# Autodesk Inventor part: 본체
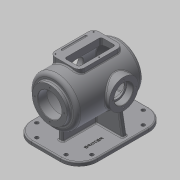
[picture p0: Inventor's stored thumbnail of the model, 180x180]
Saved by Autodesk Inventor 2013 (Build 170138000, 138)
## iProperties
Created: 2016-02
Part Number: 본체
Material: 일반
Document SubType Name: Modeling
Designer: mduedu
Density: 1 g/cm^3
Mass: 1523.86 g
Surface Area: 2907.51 cm^2
Volume: 1523.86 cm^3
Author: mduedu
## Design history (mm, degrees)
sketch "스케치2"
  geometry: L1 (0, 100)-(0, -100); L2 (65, -75.993)-(65, 100); L3 (65, 100)-(0, 100); A1 r 100 centre (0, 0) between (0, -100) and (65, -75.993); 2 further points
  constraints: 6 end point, 2 midpoint, 2 point on circle, 1 centre point, 1 coincident, 1 horizontal, 1 parallel, 1 vertical
  dimensions: "d3" = 200 distance of L1.start L1.end; "d5" = 130 diameter of L2 L1; "d6" = 100 radius of A1
revolve "회전1" sketch "스케치2" stored, may be unused: angle "d7" = 90 deg
sketch "스케치3"
  geometry: C1 r 47.5 at (0, 0); 1 further point
  constraints: 1 centre point, 1 coincident
  dimensions: "d8" = 95 diameter of C1
extrude "돌출2" join sketch "스케치3" distance "d10" = 10; taper "d11" = 0 deg
sketch "스케치5"
  geometry: L1 (47.5, 110)-(47.5, 100) reference; L2 (47.5, 100)-(65, 100) reference; L3 (65, 100)-(65, -75.993) reference; L4 (-65, -75.993)-(-65, 100) reference; L5 (-65, 100)-(-47.5, 100) reference; L6 (-47.5, 100)-(-47.5, 110) reference; L7 (-47.5, 110)-(47.5, 110) reference; L8 (55, 85)-(55, -71.239); L9 (0, 85)-(55, 85); L10 (0, 85)-(0, -90); A1 r 100 centre (0, 0) between (0, -100) and (65, -75.993) reference; A2 r 100 centre (0, 0) between (-65, -75.993) and (0, -100) reference; A3 r 90 centre (0, 0) between (0, -90) and (55, -71.239); 1 further point
  constraints: 6 end point, 2 point on circle, 1 centre point, 1 parallel, 1 perpendicular, 1 point on line, 1 vertical
  dimensions: "d13" = 10 distance between parallel lines of L3 L8; "d14" = 10 radial gap between concentric circles of A3 A1; "d15" = 15 distance between parallel lines of L9 L2
revolve "회전2" sketch "스케치5" stored, may be unused: angle "d16" = 90 deg
hole "구멍1" diameter "d19" = 65; stored, may be unused: countersink angle "d23" = 90 deg, drill point angle "d25" = 118 deg; dims "d17" = 10, "d18" = 10, "d20" = 6, "d21" = 4, "d22" = 2, "d24" = 8
node "작업 평면1"
sketch "스케치6"
  geometry: L1 (47.5, 110)-(-47.5, 110) reference; C1 r 40 at (0, -17); 1 further point
  constraints: 1 centre point, 1 vertical alignment
  dimensions: "d27" = 80 diameter of C1; "d29" = 127 distance from line of C1.centre L1
extrude "돌출3" join sketch "스케치6" stored distance "d30" = 10; taper "d31" = 0 deg
hole "구멍2" diameter "d34" = 42; stored, may be unused: countersink angle "d38" = 90 deg, drill point angle "d40" = 118 deg; dims "d32" = 10, "d33" = 10, "d35" = 6, "d36" = 52, "d37" = 18, "d39" = 8
sketch "스케치7" dims "d41" = 65
  geometry: C1 r 40 at (0, 0) reference; 3 further points
  constraints: 2 vertical alignment, 1 coincident, 2 other
hole "구멍3" sketch "스케치7" at (0, 32.5) diameter "d43" = 3.242; stored, may be unused: countersink angle "d47" = 90 deg, drill point angle "d49" = 118 deg; dims "d44" = 11, "d45" = 13, "d46" = 18, "d48" = 13
sketch "스케치8" dims "d53" = 80
  geometry: 3 further points
  constraints: 2 vertical alignment, 1 coincident, 2 other
hole "구멍4" sketch "스케치8" at (0, 40) diameter "d56" = 3.242; stored, may be unused: countersink angle "d60" = 90 deg, drill point angle "d62" = 118 deg; dims "d57" = 11, "d58" = 13, "d59" = 18, "d61" = 13
fillet "모깎기1" dims "d66" = 10
fillet "모깎기2" dims "d67" = 3
fillet "모깎기3" dims "d68" = 0.3
chamfer "모따기1" distance "d69" = 1; stored, may be unused: second distance "d70" = 2, angle "d71" = 45 deg
node "작업 평면5"
sketch "스케치23"
  geometry: L1 (6, 80)-(-6, 80); L2 (-6, 80)-(-6, -60); L3 (-6, -60)-(6, -60); L4 (6, -60)-(6, 80); L5 (-55, 100)-(55, 100) reference; 2 further points
  constraints: 8 end point, 2 parallel, 1 horizontal, 1 midpoint, 1 perpendicular, 1 vertical alignment
  dimensions: "d177" = 12 distance of L1.start L1.end; "d179" = 140 distance of L3.end L1.start; "d180" = 20 distance between parallel lines of L1 L5
extrude "돌출14" join sketch "스케치23" stored distance "d181" = 10; taper "d182" = 0 deg
node "작업 평면6"
sketch "스케치15"
  geometry: L1 (-30, 60)-(50, 60); L2 (50, 60)-(50, -60); L3 (50, -60)-(-30, -60); L4 (-30, -60)-(-30, 60); 3 further points
  constraints: 8 end point, 2 parallel, 1 horizontal, 1 horizontal alignment, 1 midpoint, 1 perpendicular, 1 vertical alignment
  dimensions: "d110" = 80 distance of L2.end L3.end; "d112" = 60 distance from line of L3 point (10, 0); "d113" = 120 distance of L1.end L2.end; "d149" = 30 distance from line of L4 point (0, 0)
extrude "돌출8" join sketch "스케치15" stored distance "d114" = 10; taper "d115" = 0 deg
fillet "모깎기7" dims "d116" = 15
sketch "스케치16"
  geometry: L1 (-30, -45)-(-30, 45) reference; L2 (-15, 60)-(35, 60) reference; L3 (35, -60)-(-15, -60) reference; L4 (-20, -45)-(-20, 45); L5 (-15, 50)-(15, 50); L6 (20, 45)-(20, -45); L7 (15, -50)-(-15, -50); L8 (50, 45)-(50, -45) reference; A1 r 15 centre (-15, -45) between (-30, -45) and (-15, -60) reference; A2 r 15 centre (-15, 45) between (-15, 60) and (-30, 45) reference; A3 r 5 centre (-15, -45) between (-20, -45) and (-15, -50); A4 r 5 centre (-15, 45) between (-15, 50) and (-20, 45); A5 r 5 centre (15, 45) between (20, 45) and (15, 50); A6 r 5 centre (15, -45) between (15, -50) and (20, -45); A7 r 15 centre (35, 45) between (50, 45) and (35, 60) reference; A8 r 15 centre (35, -45) between (35, -60) and (50, -45) reference
  constraints: 8 end point, 8 point on circle, 4 centre point, 2 equal radius, 3 other
  dimensions: "d137" = 10 distance between parallel lines of L4 L1; "d150" = 40 distance between parallel lines of L6 L4; "d151" = 100 distance between parallel lines of L7 L5
extrude "돌출9" cut sketch "스케치16" stored distance "d118" = 10; taper "d119" = 0 deg
fillet "모깎기8" dims "d120" = 3
sketch "스케치17"
  geometry: L1 (-30, -45)-(-30, 45) reference; L2 (-20, 45)-(-20, -45) reference; L3 (-15, -50)-(15, -50) reference; L4 (20, -45)-(20, 45) reference; L5 (15, 50)-(-15, 50) reference; L6 (-15, 60)-(35, 60) reference; L7 (35, -60)-(-15, -60) reference; L8 (15, 55)-(-15, 55); L9 (-25, 45)-(-25, -45); L10 (-15, -55)-(15, -55); L11 (25, -45)-(25, 45); L12 (50, 45)-(50, -45) reference; L13 (35, 55)-(-15, 55); L14 (-25, 45)-(-25, -45); L15 (-15, -55)-(35, -55); L16 (45, -45)-(45, 45); A1 r 5 centre (-15, 45) between (-15, 50) and (-20, 45) reference; A2 r 5 centre (-15, -45) between (-20, -45) and (-15, -50) reference; A3 r 5 centre (15, -45) between (15, -50) and (20, -45) reference; A4 r 5 centre (15, 45) between (20, 45) and (15, 50) reference; A5 r 15 centre (-15, 45) between (-15, 60) and (-30, 45) reference; A6 r 15 centre (-15, -45) between (-30, -45) and (-15, -60) reference; A7 r 10 centre (-15, 45) between (-15, 55) and (-25, 45); A8 r 10 centre (-15, -45) between (-25, -45) and (-15, -55); A9 r 10 centre (15, -45) between (15, -55) and (25, -45); A10 r 10 centre (15, 45) between (25, 45) and (15, 55); A11 r 15 centre (35, 45) between (50, 45) and (35, 60) reference; A12 r 15 centre (35, -45) between (35, -60) and (50, -45) reference; A13 r 10 centre (-15, 45) between (-15, 55) and (-25, 45); A14 r 10 centre (-15, -45) between (-25, -45) and (-15, -55); A15 r 10 centre (35, -45) between (35, -55) and (45, -45); A16 r 10 centre (35, 45) between (45, 45) and (35, 55); 6 further points
  constraints: 18 point on circle, 16 end point, 8 centre point, 4 midpoint, 4 tangent, 11 other
  dimensions: "d138" = 5 distance between parallel lines of L8 L6; "d157" = 5 distance between parallel lines of L12 L16
hole "구멍5" sketch "스케치17" at (-25, 0), (42.071, 52.071), (42.071, -52.071) diameter "d122" = 3.242; stored, may be unused: countersink angle "d126" = 90 deg, drill point angle "d128" = 118 deg; dims "d123" = 9, "d124" = 13, "d125" = 18, "d127" = 11
sketch "스케치19"
  geometry: L1 (-50, 70)-(-35, 70) reference; L2 (-50, 42.603)-(-50, 70) reference; C1 r 2.5 at (-43, 70); 1 further point
  constraints: 1 centre point, 1 point on line
  dimensions: "d152" = 5 diameter of C1; "d153" = 7 distance from line of C1.centre L2
extrude "돌출11" cut sketch "스케치19" stored distance "d154" = 70; taper "d155" = 0 deg
fillet "모깎기11" dims "d156" = 2.5
sketch "스케치20"
  geometry: L1 (-90, 120)-(90, 120); L2 (90, 120)-(90, -120); L3 (90, -120)-(-90, -120); L4 (-90, -120)-(-90, 120); 3 further points
  constraints: 8 end point, 2 parallel, 2 vertical alignment, 1 coincident, 1 horizontal, 1 midpoint, 1 perpendicular
  dimensions: "d162" = 180 distance of L1.start L1.end; "d164" = 240 distance of L1.end L2.end; "d165" = 120 distance from line of L1 point (0, 0)
extrude "돌출12" join sketch "스케치20" distance "d166" = 10; taper "d167" = 0 deg
fillet "모깎기12" dims "d168" = 50
node "작업 평면8"
  node "작업축1"
sketch "스케치24"
  geometry: L1 (128, 34.121)-(127.026, 32.5) reference; L2 (127.026, 32.5)-(128, 30.879) reference; L3 (128, 30.879)-(141, 30.879) reference; L4 (141, 30.879)-(141, 27) reference; L5 (141, 27)-(140, 26) reference; L6 (140, 26)-(123.3, 26) reference; L7 (123, 25.7)-(123, 21) reference; L8 (123, 21)-(116.833, 21) reference; L9 (86, 51.235)-(86, 70) reference; L10 (86, 70)-(106.5, 70) reference; L11 (111.5, 70)-(116, 70) reference; L12 (116, 70)-(116, 42.603) reference; L13 (118.678, 40)-(141, 40) reference; L14 (141, 40)-(141, 34.121) reference; L15 (141, 34.121)-(128, 34.121) reference; L16 (4, -34.121)-(4.974, -32.5) reference; L17 (4.974, -32.5)-(4, -30.879) reference; L18 (4, -30.879)-(-9, -30.879) reference; L19 (-9, -30.879)-(-9, -27) reference; L20 (-9, -27)-(-8, -26) reference; L21 (-8, -26)-(8.7, -26) reference; L22 (9, -25.7)-(9, -21) reference; L23 (9, -21)-(15.167, -21) reference; L24 (116.833, -21)-(123, -21) reference; L25 (123, -21)-(123, -25.7) reference; L26 (123.3, -26)-(140, -26) reference; L27 (140, -26)-(141, -27) reference; L28 (141, -27)-(141, -30.879) reference; L29 (141, -30.879)-(128, -30.879) reference; L30 (128, -30.879)-(127.026, -32.5) reference; L31 (127.026, -32.5)-(128, -34.121) reference; L32 (128, -34.121)-(141, -34.121) reference; L33 (141, -34.121)-(141, -40) reference; L34 (141, -40)-(118.678, -40) reference; L35 (72, -64.722)-(72, -100) reference; L36 (72, -100)-(156, -100) reference; L37 (156, -100)-(156, -110) reference; L38 (156, -110)-(-24, -110) reference; L39 (-24, -110)-(-24, -100) reference; L40 (-24, -100)-(60, -100) reference; L41 (60, -100)-(60, -64.722) reference; L42 (13.322, -40)-(-9, -40) reference; L43 (-9, -40)-(-9, -34.121) reference; L44 (-9, -34.121)-(4, -34.121) reference; L45 (4.974, 32.5)-(4, 34.121) reference; L46 (4, 34.121)-(-9, 34.121) reference; L47 (-9, 34.121)-(-9, 40) reference; L48 (-9, 40)-(13.322, 40) reference; L49 (36, 59.456)-(36, 70) reference; L50 (36, 70)-(46, 70) reference; L51 (46, 70)-(46, 51.235) reference; L52 (15.167, 21)-(9, 21) reference; L53 (9, 21)-(9, 25.7) reference; L54 (8.7, 26)-(-8, 26) reference; L55 (-8, 26)-(-9, 27) reference; L56 (-9, 27)-(-9, 30.879) reference; L57 (-9, 30.879)-(4, 30.879) reference; L58 (4, 30.879)-(4.974, 32.5) reference; L59 (-1, -40)-(-11.58, -100); A1 r 0.3 centre (123.3, 25.7) between (123.3, 26) and (123, 25.7) reference; A2 r 55 centre (66, 0) between (116.833, 21) and (86, 51.235) reference; A3 r 2.5 centre (109, 70) between (106.5, 70) and (111.5, 70) reference; A4 r 3 centre (119, 42.603) between (116, 42.603) and (116.516, 40.92) reference; A5 r 0.3 centre (8.7, -25.7) between (8.7, -26) and (9, -25.7) reference; A6 r 55 centre (66, 0) between (15.167, -21) and (116.833, -21) reference; A7 r 0.3 centre (123.3, -25.7) between (123, -25.7) and (123.3, -26) reference; A8 r 65 centre (66, 0) between (72, -64.722) and (116.354, -41.103) reference; A9 r 65 centre (66, 0) between (15.646, -41.103) and (60, -64.722) reference; A10 r 65 centre (66, 0) between (34.456, 56.833) and (15.646, 41.103) reference; A11 r 3 centre (33, 59.456) between (34.456, 56.833) and (36, 59.456) reference; A12 r 55 centre (66, 0) between (46, 51.235) and (15.167, 21) reference; A13 r 0.3 centre (8.7, 25.7) between (9, 25.7) and (8.7, 26) reference; 1 further point
  constraints: 2 end point, 2 point on line, 4 other
  dimensions: "d184" = 8 distance of L59.start L42.end; "d185" = 100 deg angle of L59 L40
feature "리브2" sketch "스케치24" dims "d186" = 1, "d187" = 12, "d188" = 0, "d189" = 0, "d190" = 1, "d191" = 1
fillet "모깎기15" dims "d192" = 3
fillet "모깎기16" dims "d193" = 3
sketch "스케치25"
  geometry: L1 (90, -70)-(90, 70) reference; L2 (40, 120)-(-40, 120) reference; L3 (-90, 70)-(-90, -70) reference; L4 (-40, -120)-(40, -120) reference; L5 (-74.004, 8)-(-9, 8) reference; L6 (-80.097, 20)-(-80.097, 14) reference; L7 (-9, 26)-(-74.004, 26) reference; L8 (-9, 57)-(-9, 26) reference; L9 (3, 63)-(-3, 63) reference; L10 (9, 26)-(9, 57) reference; L11 (74.004, 26)-(9, 26) reference; L12 (80.097, 14)-(80.097, 20) reference; L13 (9, 8)-(74.004, 8) reference; L14 (9, -77)-(9, 8) reference; L15 (-3, -83)-(3, -83) reference; L16 (-9, 8)-(-9, -77) reference; L17 (-40, 105)-(40, 105); L18 (75, 70)-(75, -70); L19 (40, -105)-(-40, -105); L20 (-75, -70)-(-75, 70); C1 r 5 at (-75, 70); C2 r 5 at (-40, 105); C3 r 5 at (40, 105); C4 r 5 at (75, 70); C5 r 5 at (75, -70); C6 r 5 at (40, -105); C7 r 5 at (-40, -105); C8 r 5 at (-75, -70); A1 r 50 centre (40, 70) between (90, 70) and (40, 120) reference; A2 r 50 centre (-40, 70) between (-40, 120) and (-90, 70) reference; A3 r 50 centre (-40, -70) between (-90, -70) and (-40, -120) reference; A4 r 50 centre (40, -70) between (40, -120) and (90, -70) reference; A5 r 6 centre (-3, 57) between (-3, 63) and (-9, 57) reference; A6 r 6 centre (3, 57) between (9, 57) and (3, 63) reference; A7 r 6 centre (3, -77) between (3, -83) and (9, -77) reference; A8 r 6 centre (-3, -77) between (-9, -77) and (-3, -83) reference; A9 r 35 centre (40, 70) between (75, 70) and (40, 105); A10 r 35 centre (40, -70) between (40, -105) and (75, -70); A11 r 35 centre (-40, -70) between (-75, -70) and (-40, -105); A12 r 35 centre (-40, 70) between (-40, 105) and (-75, 70); 5 further points; 4 other entities
  constraints: 12 centre point, 8 coincident, 8 end point, 8 point on circle, 7 equal radius, 11 other
  dimensions: "d194" = 15 distance between parallel lines of L17 L2; "d195" = 10 diameter of C1
extrude "돌출15" cut sketch "스케치25" stored distance "d197" = 10; taper "d198" = 0 deg
fillet "모깎기14" dims "d170" = 3
sketch "스케치22"
  geometry: L1 (90, -70)-(90, 70) reference; 2 further points
  constraints: 1 other
  dimensions: "d174" = 40 distance from line of L1 point (50, -40); "d199" = 40 vertical distance of point (50, -40) point (0, 0)
feature "엠보싱2" sketch "스케치22" dims "d13" = 10, "d175" = 0.5, "d176" = 0
node "솔리드2"
pattern_circular "원형 패턴1" dims angle "d51" = 360 deg
mirror "대칭1"
pattern_circular "원형 패턴2" dims angle "d64" = 360 deg
mirror "대칭3"
node "투영된 루프2"
node "절단 모서리 투영1"
node "절단 모서리 투영2"
node "절단 모서리 투영3"
node "절단 모서리 투영4"
other parameters: "d26" = 75, "d183" = 0
